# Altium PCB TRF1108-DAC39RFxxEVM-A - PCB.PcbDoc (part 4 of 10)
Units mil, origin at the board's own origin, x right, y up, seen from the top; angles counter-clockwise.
Board outline 4951.22 x 2726.56 mil, 16 copper layers (Top Layer, L2 GND1, L3 PWR1, L4 GND2, L5 PWR2, L6 GND3, L7 Ctrl Signal 1, L8 GND4, L9 GND5, L10 Ctrl Signal 2, L11 GND6, L12 PWR3, L13 GND7, L14 PWR4, L15 GND8, Bottom Layer), stack 80.2 mil thick; 705 components, 433 nets, 3633 pads, 1678 vias.
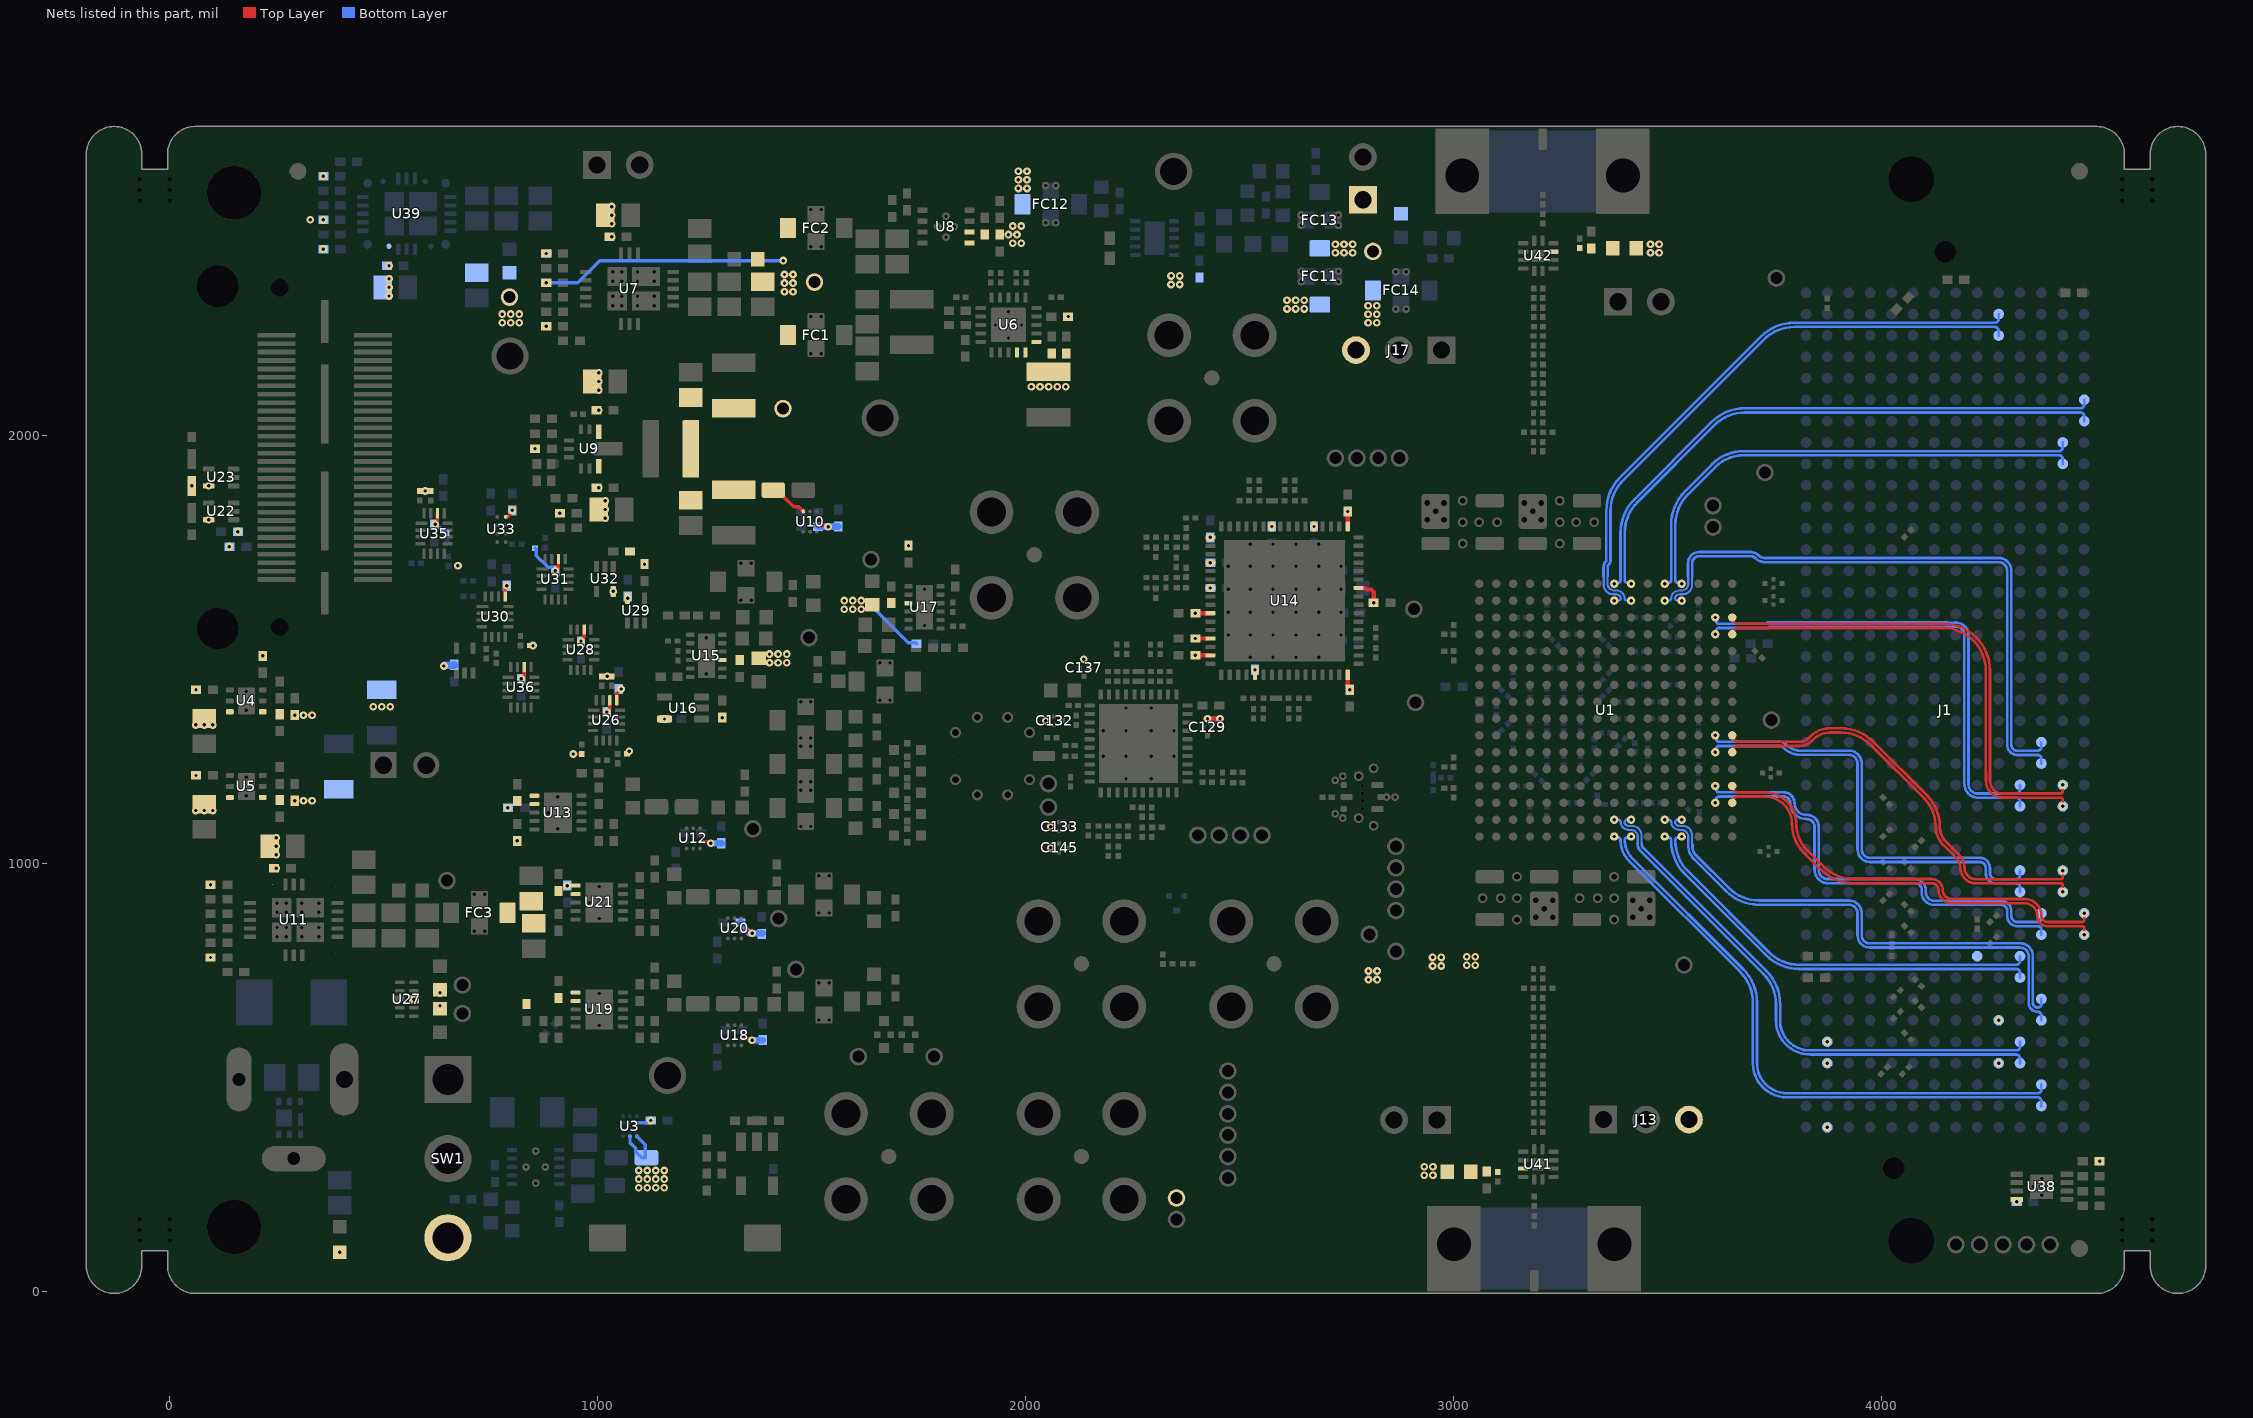
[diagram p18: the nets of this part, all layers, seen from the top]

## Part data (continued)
Logo3: library part cmp00102, "FCC_disclaimer", Alt Manufacturer=-
Logo4: library part cmp00317, Alt Manufacturer=-, PartNumber="ESD Logo"
Logo5: library part cmp00101, Alt Manufacturer=-, PartNumber=WEEE_Minimum
LOGO6: library part cmp00103, "CE_Mark", Alt Manufacturer=-
Logo7: library part cmp00104, "Texas Instrument Corporate Signature", Alt Manufacturer=-, PartNumber="TI Bug"
MP1: library part cmp00111, "Heat Sink Passive BGA Straight Adhesive 9.3C/W Black Anodized", Alt Manufacturer=-, Manufacturer="Advanced Thermal Solutions", Supplier Part Number 1=ATS1230-ND
MP5: library part cmp00110, "Fan Tubeaxial 5VDC Square - 17mm L x 17mm H Sleeve 0.636 CFM (0.018m³/min) 2 Wire Leads", Alt Manufacturer=-, Manufacturer="Nidec Copal", PartNumber=F17HA-05HC, Supplier Part Number 1=563-1426-ND
PP1 PP2 PP3 PP4 PP5 PP6 PP7 PP8 PP9 PP10 PP11 PP12 PP13 PP14 PP15 PP16 PP17 PP18 PP19 PP20 PP21 PP22 PP23 PP24 PP25 PP26 PP27 PP28 PP29 PP30 PP31 PP32 PP33 PP34 PP35 PP36 PP37 PP38 PP39 PP40 PP41 PP42 PP43 PP44 PP45 PP46 PP47 PP48 PP49 PP50 PP51: library part cmp00025, "Probe Point that can be used in lue of a test point", Alt Manufacturer=-
Q1: library part CMP-0000207-1, "MOSFET, N-CH, 20 V, 10 A, DQK0006C (WSON-6)", Alternate Manufacturer=None, Manufacturer="Texas Instruments", Supplier Part Number 1=CSD15571Q2-ND, Value1=19, Value2="2.5 nC"
R1 R36 R57: library part OtherRs00002, "RES SHUNT, 0603, 0.002 OHM, 1%,", Manufacturer="Stackpole Electronics Inc", Operating Temperature="-55°C ~ 155°C", Power (Watts)="0.333W, 1/3W", Ratings=AEC-Q200, Resistance="2 mΩ", Supplier Part Number 1=738-CSS0603FT2L00CT-ND, Temperature Coefficient=±150ppm/°C, Tolerance=±1%
R2: library part RSMD040200026, "RES SMD 1M OHM 1% 1/10W 0402", Manufacturer="Panasonic Electronic Components", Operating Temperature="-55°C ~ 155°C", Power (Watts)="0.1W, 1/10W", Ratings=AEC-Q200, Resistance="1 MΩ", Supplier Part Number 1=P1.00MLCT-ND, Temperature Coefficient=±100ppm/°C, Tolerance=±1%
R3: library part RSMD040202774, "RES SMD 45.3K OHM 1% 1/10W 0402", Manufacturer="Panasonic Electronic Components", Operating Temperature="-55°C ~ 155°C", Power (Watts)="0.1W, 1/10W", Ratings=AEC-Q200, Resistance="45.3 kΩ", Supplier Part Number 1=P45.3KLCT-ND, Temperature Coefficient=±100ppm/°C, Tolerance=±1%
R4 R8 R9 R11 R15 R17 R20 R25 R28 R31 R34 R35 R39 R48 R49 R51 R58 R84 R86 R88 R89 R91 R97 R106 R111 R112 R114 R115 R150 R151 R156 R161 R163 R178 R181 R183 R189 R210 R213 R214 R215: library part RSMD040202585, "RES SMD 4.7K OHM 5% 1/10W 0402", Manufacturer="Panasonic Electronic Components", Operating Temperature="-55°C ~ 155°C", Power (Watts)="0.1W, 1/10W", Ratings=AEC-Q200, Resistance="4.7 kΩ", Supplier Part Number 1=P4.7KJCT-ND, Temperature Coefficient=±200ppm/°C, Tolerance=±5%
R5: library part RSMD080500627, "RES SMD 2.2K OHM 1% 1/8W 0805", Manufacturer="Panasonic Electronic Components", Operating Temperature="-55°C ~ 155°C", Power (Watts)="0.125W, 1/8W", Ratings=AEC-Q200, Resistance="2.2 kΩ", Temperature Coefficient=±100ppm/°C, Tolerance=±1%
R6 R7: library part RSMD120607282, "RES 0 OHM JUMPER 1206 SMD", Manufacturer="Vishay Dale", Operating Temperature="-55°C ~ 155°C", Power (Watts)="0.25W, 1/4W", Ratings=AEC-Q200, Resistance="0 Ω", Temperature Coefficient=-, Tolerance=Jumper
R10: library part RSMD040201180, "RES SMD 2M OHM 5% 1/10W 0402", Manufacturer="Panasonic Electronic Components", Operating Temperature="-55°C ~ 155°C", Power (Watts)="0.1W, 1/10W", Ratings=AEC-Q200, Resistance="2 MΩ", Supplier Part Number 1=P2.0MJCT-ND, Temperature Coefficient="-400/ +150ppm/°C", Tolerance=±5%
R12: library part RSMD040202017, "RES SMD 3.6M OHM 5% 1/10W 0402", Manufacturer="Panasonic Electronic Components", Operating Temperature="-55°C ~ 155°C", Power (Watts)="0.1W, 1/10W", Ratings=AEC-Q200, Resistance="3.6 MΩ", Supplier Part Number 1=P3.6MJCT-ND, Temperature Coefficient="-400/ +150ppm/°C", Tolerance=±5%
R13 R14: library part RSMD040200111, "RES SMD 1.2M OHM 5% 1/10W 0402", Manufacturer="Panasonic Electronic Components", Operating Temperature="-55°C ~ 155°C", Power (Watts)="0.1W, 1/10W", Ratings=AEC-Q200, Resistance="1.2 MΩ", Supplier Part Number 1=P1.2MJCT-ND, Temperature Coefficient="-400/ +150ppm/°C", Tolerance=±5%
R16 R170: library part RSMD040200354, "RES SMD 100K OHM 5% 1/10W 0402", Manufacturer="Panasonic Electronic Components", Operating Temperature="-55°C ~ 155°C", Power (Watts)="0.1W, 1/10W", Ratings=AEC-Q200, Resistance="100 kΩ", Supplier Part Number 1=P100KJCT-ND, Temperature Coefficient=±200ppm/°C, Tolerance=±5%
R18 R37 R38 R43 R54 R55 R93 R94 R101 R102 R103 R107 R113 R116 R171 R172 R173 R174 R204: library part RSMD040200001, "RES SMD 0 OHM JUMPER 1/10W 0402", Manufacturer="Panasonic Electronic Components", Operating Temperature="-55°C ~ 155°C", Power (Watts)="0.1W, 1/10W", Ratings=AEC-Q200, Resistance="0 Ω", Supplier Part Number 1=P0.0JCT-ND, Temperature Coefficient=-, Tolerance=Jumper
R19 R21 R22 R23 R24 R26 R46 R63 R65 R68 R70 R119 R120 R121 R124 R133 R136 R142 R143 R144 R145 R146 R147 R152 R153 R154 R155 R157 R158 R159 R160 R162 R164 R165 R166 R167 R168 R169 R175 R186 R187 R200 R205 R206 R207 R209 R211 R212 R216 R217 R218 R219 R220 R221 R222 R223 R224 R225 R226 R227 R228 R229 R230 R231 R236 R250 R255: library part RSMD020101699, "RES SMD 0 OHM JUMPER 1/20W 0201", Manufacturer="Panasonic Electronic Components", Operating Temperature="-55°C ~ 125°C", Power (Watts)="0.05W, 1/20W", Resistance="0 Ω", Supplier Part Number 1=P15979CT-ND, Tolerance=Jumper
R27 R29 R182: library part RSMD040201047, "RES SMD 18.2K OHM 1% 1/10W 0402", Manufacturer="Panasonic Electronic Components", Operating Temperature="-55°C ~ 155°C", Power (Watts)="0.1W, 1/10W", Ratings=AEC-Q200, Resistance="18.2 kΩ", Supplier Part Number 1=P18.2KLCT-ND, Temperature Coefficient=±100ppm/°C, Tolerance=±1%
R30 R41 R53 R180: library part RSMD040202616, "RES SMD 4.87K OHM 1% 1/10W 0402", Manufacturer="Panasonic Electronic Components", Operating Temperature="-55°C ~ 155°C", Power (Watts)="0.1W, 1/10W", Ratings=AEC-Q200, Resistance="4.87 kΩ", Supplier Part Number 1=P4.87KLCT-ND, Temperature Coefficient=±100ppm/°C, Tolerance=±1%
R32: library part RSMD040202088, "RES SMD 30.9K OHM 1% 1/10W 0402", Manufacturer="Panasonic Electronic Components", Operating Temperature="-55°C ~ 155°C", Power (Watts)="0.1W, 1/10W", Ratings=AEC-Q200, Resistance="30.9 kΩ", Supplier Part Number 1=P30.9KLCT-ND, Temperature Coefficient=±100ppm/°C, Tolerance=±1%
R33 R40 R44 R45 R47 R56 R82 R83 R95 R104: library part RSMD040200316, "RES 10K OHM 1% 1/10W 0402", Manufacturer="Panasonic Electronic Components", Operating Temperature="-55°C ~ 175°C", Power (Watts)="0.1W, 1/10W", Ratings=AEC-Q200, Resistance="10 kΩ", Supplier Part Number 1=10-ERJ-H2RF1002XCT-ND, Temperature Coefficient=±100ppm/°C, Tolerance=±1%
R42: library part RSMD040200983, "RES SMD 17.4K OHM 1% 1/10W 0402", Manufacturer="Panasonic Electronic Components", Operating Temperature="-55°C ~ 155°C", Power (Watts)="0.1W, 1/10W", Ratings=AEC-Q200, Resistance="17.4 kΩ", Supplier Part Number 1=P17.4KLCT-ND, Temperature Coefficient=±100ppm/°C, Tolerance=±1%
R50: library part RSMD040203921, "RES SMD 9.31K OHM 1% 1/10W 0402", Manufacturer="Panasonic Electronic Components", Operating Temperature="-55°C ~ 155°C", Power (Watts)="0.1W, 1/10W", Ratings=AEC-Q200, Resistance="9.31 kΩ", Supplier Part Number 1=P9.31KLCT-ND, Temperature Coefficient=±100ppm/°C, Tolerance=±1%
R52: library part RSMD040203072, "RES SMD 52.3K OHM 1% 1/10W 0402", Manufacturer="Panasonic Electronic Components", Operating Temperature="-55°C ~ 155°C", Power (Watts)="0.1W, 1/10W", Ratings=AEC-Q200, Resistance="52.3 kΩ", Supplier Part Number 1=P52.3KLCT-ND, Temperature Coefficient=±100ppm/°C, Tolerance=±1%
R59: library part RSMD040203879, "RES SMD 88.7K OHM 1% 1/10W 0402", Manufacturer="Panasonic Electronic Components", Operating Temperature="-55°C ~ 155°C", Power (Watts)="0.1W, 1/10W", Ratings=AEC-Q200, Resistance="88.7 kΩ", Supplier Part Number 1=P88.7KLCT-ND, Temperature Coefficient=±100ppm/°C, Tolerance=±1%
R60: library part RSMD040200547, "RES SMD 12.4K OHM 1% 1/10W 0402", Manufacturer="Panasonic Electronic Components", Operating Temperature="-55°C ~ 155°C", Power (Watts)="0.1W, 1/10W", Ratings=AEC-Q200, Resistance="12.4 kΩ", Supplier Part Number 1=P12.4KLCT-ND, Temperature Coefficient=±100ppm/°C, Tolerance=±1%
R61: library part RSMD040200530, "RES 12K OHM 0.5% 1/10W 0402 SMD", Manufacturer="Panasonic Electronic Components", Operating Temperature="-55°C ~ 155°C", Power (Watts)="0.1W, 1/10W", Ratings=AEC-Q200, Resistance="12 kΩ", Supplier Part Number 1=10-ERJ-U2RD1202XCT-ND, Temperature Coefficient=±50ppm/°C, Tolerance=±0.5%
R62 R66 R67 R71 R125 R126 R129 R130 R131 R132 R138 R139 R140 R141: library part RSMD020100177, "RES SMD 49.9 OHM 1% 1/20W 0201", Manufacturer="Panasonic Electronic Components", Operating Temperature="-55°C ~ 125°C", Power (Watts)="0.05W, 1/20W", Resistance="49.9 Ω", Supplier Part Number 1=P123049CT-ND, Temperature Coefficient=±200ppm/°C, Tolerance=±1%
R64 R69 R122 R123 R128: library part RSMD020100289, "RES SMD 100 OHM 1% 1/20W 0201", Manufacturer="Panasonic Electronic Components", Operating Temperature="-55°C ~ 125°C", Power (Watts)="0.05W, 1/20W", Resistance="100 Ω", Supplier Part Number 1=P122654CT-ND, Temperature Coefficient=±200ppm/°C, Tolerance=±1%
R72 R73 R74 R75 R76 R77 R78 R79 R80 R81: library part RSMD020100156, "RES SMD 120 OHM 1% 1/20W 0201", Manufacturer="Panasonic Electronic Components", Operating Temperature="-55°C ~ 125°C", Power (Watts)="0.05W, 1/20W", Resistance="120 Ω", Supplier Part Number 1=P122692CT-ND, Temperature Coefficient=±200ppm/°C, Tolerance=±1%
R85 R90: library part RSMD040201710, "RES SMD 255K OHM 1% 1/10W 0402", Manufacturer="Panasonic Electronic Components", Operating Temperature="-55°C ~ 155°C", Power (Watts)="0.1W, 1/10W", Ratings=AEC-Q200, Resistance="255 kΩ", Supplier Part Number 1=P255KLCT-ND, Temperature Coefficient=±100ppm/°C, Tolerance=±1%
R87 R92: library part RSMD040202914, "RES SMD 499K OHM 1% 1/10W 0402", Manufacturer="Panasonic Electronic Components", Operating Temperature="-55°C ~ 155°C", Power (Watts)="0.1W, 1/10W", Ratings=AEC-Q200, Resistance="499 kΩ", Supplier Part Number 1=P499KLCT-ND, Temperature Coefficient=±100ppm/°C, Tolerance=±1%
R96 R105: library part OtherRs00005, "RES SHUNT, 0603, 0.02 OHM, 1%, 0", Manufacturer="Stackpole Electronics Inc", Operating Temperature="-55°C ~ 155°C", Power (Watts)="0.333W, 1/3W", Ratings=AEC-Q200, Resistance="20 mΩ", Supplier Part Number 1=738-CSS0603FT20L0CT-ND, Temperature Coefficient=±75ppm/°C, Tolerance=±1%
R98 R108: library part RSMD040200493, "RES SMD 115K OHM 1% 1/10W 0402", Manufacturer="Panasonic Electronic Components", Operating Temperature="-55°C ~ 155°C", Power (Watts)="0.1W, 1/10W", Ratings=AEC-Q200, Resistance="115 kΩ", Supplier Part Number 1=P115KLCT-ND, Temperature Coefficient=±100ppm/°C, Tolerance=±1%
R99 R109: library part RSMD040202211, "RES SMD 33K OHM 1% 1/10W 0402", Manufacturer="Panasonic Electronic Components", Operating Temperature="-55°C ~ 155°C", Power (Watts)="0.1W, 1/10W", Ratings=AEC-Q200, Resistance="33 kΩ", Supplier Part Number 1=P33.0KLCT-ND, Temperature Coefficient=±100ppm/°C, Tolerance=±1%
R100 R110: library part RSMD040203274, "RES SMD 6.65K OHM 1% 1/10W 0402", Manufacturer="Panasonic Electronic Components", Operating Temperature="-55°C ~ 155°C", Power (Watts)="0.1W, 1/10W", Ratings=AEC-Q200, Resistance="6.65 kΩ", Supplier Part Number 1=P6.65KLCT-ND, Temperature Coefficient=±100ppm/°C, Tolerance=±1%
R117 R118: library part RSMD020100281, "RES SMD 66.5 OHM 1% 1/20W 0201", Manufacturer="Panasonic Electronic Components", Operating Temperature="-55°C ~ 125°C", Power (Watts)="0.05W, 1/20W", Resistance="66.5 Ω", Supplier Part Number 1=P123123CT-ND, Temperature Coefficient=±200ppm/°C, Tolerance=±1%
R127 R135: library part RSMD020100110, "RES SMD 82.5 OHM 1% 1/20W 0201", Manufacturer="Panasonic Electronic Components", Operating Temperature="-55°C ~ 125°C", Power (Watts)="0.05W, 1/20W", Resistance="82.5 Ω", Supplier Part Number 1=P123178CT-ND, Temperature Coefficient=±200ppm/°C, Tolerance=±1%
R134 R137: library part RSMD020100121, "RES SMD 130 OHM 1% 1/20W 0201", Manufacturer="Panasonic Electronic Components", Operating Temperature="-55°C ~ 125°C", Power (Watts)="0.05W, 1/20W", Resistance="130 Ω", Supplier Part Number 1=P122712CT-ND, Temperature Coefficient=±200ppm/°C, Tolerance=±1%
R148 R149: library part RSMD060301484, "RES SMD 2.2K OHM 5% 1/10W 0603", Manufacturer="Panasonic Electronic Components", Operating Temperature="-55°C ~ 155°C", Power (Watts)="0.1W, 1/10W", Ratings=AEC-Q200, Resistance="2.2 kΩ", Supplier Part Number 1=P2.2KGCT-ND, Temperature Coefficient=±200ppm/°C, Tolerance=±5%
R176: library part RSMD040200006, "RES SMD 1K OHM 1% 1/10W 0402", Manufacturer="Panasonic Electronic Components", Operating Temperature="-55°C ~ 155°C", Power (Watts)="0.1W, 1/10W", Ratings=AEC-Q200, Resistance="1 kΩ", Supplier Part Number 1=P1.00KLCT-ND, Temperature Coefficient=±100ppm/°C, Tolerance=±1%
R177: library part RSMD040202006, "RES SMD 3.6K OHM 1% 1/10W 0402", Manufacturer="Panasonic Electronic Components", Operating Temperature="-55°C ~ 155°C", Power (Watts)="0.1W, 1/10W", Ratings=AEC-Q200, Resistance="3.6 kΩ", Supplier Part Number 1=P3.60KLCT-ND, Temperature Coefficient=±100ppm/°C, Tolerance=±1%
R179: library part CMP-0026220-2, "RES, 28.7 k, 1%, 0.063 W, AEC-Q200 Grade 0, 0402", Manufacturer=Vishay-Dale, Power_W=63mW, Supplier Part Number 1=541-28.7KLCT-ND, TempCo="100 ppm/C", Tolerance_%=1%, Value2=0.063W, Value_Code=28k7, ValueDisplayed=28.7k
R184: library part CMP-0022744-5, "RES, 10.5 k, 1%, 0.1 W, 0603", Manufacturer=Yageo, Power_W=100mW, Supplier Part Number 1=311-10.5KHRCT-ND, TempCo="100 ppm/C", Tolerance_%=1%, Value2=0.1W, Value_Code=10k5, ValueDisplayed=10.5k
R185: library part CMP-0023000-5, "RES, 2.00 k, 1%, 0.1 W, 0603", Manufacturer=Yageo, Power_W=100mW, Supplier Part Number 1=311-2.00KHRCT-ND, TempCo="100 ppm/C", Tolerance_%=1%, Value2=0.1W, Value_Code=2k00, ValueDisplayed=2.00k
R192 R237 R242 R256: library part RSMD020100157, "RES SMD 140 OHM 1% 1/20W 0201", Manufacturer="Panasonic Electronic Components", Operating Temperature="-55°C ~ 125°C", Power (Watts)="0.05W, 1/20W", Resistance="140 Ω", Supplier Part Number 1=P122727CT-ND, Temperature Coefficient=±200ppm/°C, Tolerance=±1%
R196 R197 R201 R202 R246 R247 R251 R252: library part RSMD020101700, "Thick Film Resistors - SMD 8.66Ohms 1/20W 0201 1%", Manufacturer=Yageo, Operating Temperature="-55°C ~ 125°C", Power (Watts)="0.05W, 1/20W", Resistance="8.66 Ω", Supplier Part Number 1=13-RC0201FR-078R66LCT-ND, Temperature Coefficient="- 100 PPM / C, + 350 PPM / C", Tolerance=±1%
R208 R232 R233 R234: library part RSMD040200370, "RES SMD 100 OHM 5% 1/10W 0402", Manufacturer="Panasonic Electronic Components", Operating Temperature="-55°C ~ 155°C", Power (Watts)="0.1W, 1/10W", Ratings=AEC-Q200, Resistance="100 Ω", Supplier Part Number 1=P100JCT-ND, Temperature Coefficient=±200ppm/°C, Tolerance=±5%
SH-J13 SH-J14 SH-J17 SH-J18: library part CMP-0003761-1, "Shunt, 2.54mm, Gold, Black", Manufacturer="Wurth Elektronik", Supplier Part Number 1=732-2678-ND
SW1: library part cmp00021, "Switch Slide SPDT 120V, 6A", Alt Manufacturer=-, Manufacturer="C&K Components", Supplier Part Number 1=CKN9628-ND
SW2: library part cmp00234, "SWITCH TACTILE SPST-NO 0.05A 24V", Alt Manufacturer=-, Manufacturer="TE Connectivity", Supplier Part Number 1=A101402CT-ND
T1: library part cmp00236, "1:2 LTCC Transformer, 4700 - 12000 MHz, 50Ω", Alt Manufacturer=-, Manufacturer=Mini-Circuits, Supplier Part Number 1=3157-NCR2-123+CT-ND
T2 T3 T4 T5: library part cmp00081, "Signal Conditioning BIAS TEE SURFACE MOUNT", Alt Manufacturer=-, Manufacturer=Mini-Circuits, Supplier Part Number 1=3157-TCBT-123+CT-ND
TP1 TP2 TP3: library part cmp00041, "Test Point, Multipurpose, Black, TH", Alt Manufacturer=-, Color=Black, Manufacturer=Keystone, Supplier Part Number 1=36-5011-ND
TP4: library part cmp00040, "Test Point, Multipurpose, Red, TH", Alt Manufacturer=-, Color=Red, Manufacturer=Keystone, Supplier Part Number 1=36-5010-ND
U1: library part cmp00276, Alt Manufacturer=-, Manufacturer="Texas Instruments"
U2: library part cmp00157, "12V, 5A, 30mΩ eFuse with Adjustable +/-15% Accurate Current Limit, DRC0010J (VSON-10)", Alt Manufacturer=-, Manufacturer="Texas Instruments"
U3 U10 U12 U18 U20: library part cmp00264, "28-V, 16-Bit, I2C Output Current, Voltage and Power Monitor With Alert in WCSP Package", Alt Manufacturer="Texas Instruments", Alt PartNumber=INA231AIYFFT, Color=-, Supplier Part Number 1=296-41263-1-ND
U4 U5: library part cmp00251, "300-mA, 18-V, Ultra-Low IQ, Low-Dropout Linear Voltage Regulator With Power-Good", Alt Manufacturer=-, Manufacturer="Texas Instruments", PartNumber=TPS7A2501DRV
U6: library part cmp00163, "Regulators 2-A, low-VIN (1.1-V), low-noise, high-accuracy, ultra-low-dropout voltage regulator with power good", Alt Manufacturer=-, Manufacturer="Texas Instruments"
U7 U11: library part cmp00201, "3-V to 17-V, 2-A/3-A Low-Noise and Low-Ripple Buck Power Module with Integrated Ferrite Bead Filter Compensation", Alt Manufacturer=-, Manufacturer="Texas Instruments", Max Supply Voltage=17V, Min Supply Voltage=3V, Nominal Supply Current=5mA, Operating Temperature Range="-55°C to +125°C", Output Voltage=0.8-5.5V, PartNumber=TPSM82913RDU, Switching Frequency=1/2.2MHz
U8: library part cmp00168, "1-A, high-PSRR, ultra-low-dropout voltage regulator with low-IQ & enable", Alt Manufacturer=-, Manufacturer="Texas Instruments"
U9: library part cmp00293, "4-V to 18-V Input, 6-A Synchronous SWIFT™ Step-Down Converter with Internally Compensated Advanced Current Mode Control", Alt Manufacturer=-, Manufacturer="Texas Instruments", Supplier Part Number 1=296-TPS543620RPYRCT-ND
U13 U19 U21: library part cmp00169, "1-A, ultra-low noise, ultra-high PSRR, RF voltage regulator", Alt Manufacturer=-, Manufacturer="Texas Instruments", Supplier Part Number 1=296-TPS7A9401DSCRCT-ND
U14: library part cmp00252, "Ultra low-noise JESD204B compliant clock jitter cleaner with integrated 2370 to 2630-MHz VCO0", Alt Manufacturer="Texas Instruments", Alt PartNumber=LMK04828BISQE/NOPB, Color=-, Supplier Part Number 1=296-40278-1-ND
U15 U17: library part cmp00189, "Low-Noise Positive- and Negative-Output Charge Pump With Integrated LDO", Alt Manufacturer=-, Manufacturer="Texas Instruments"
U16: library part cmp00128, "Single Bus Inverting Buffer Gate", Alt Manufacturer=-, Manufacturer="Texas Instruments"
U22 U23 U29 U32 U34: library part cmp00309, "Single Bus Buffer Gate With 3-State Outputs", Alt Manufacturer=-, Manufacturer="Texas Instruments"
U24: library part cmp00312, "Signal Conditioning 50 ohm 2 terminal Power Splitter", Alt Manufacturer=-, Manufacturer=Susumu, Supplier Part Number 1=754-PS1608GT2-R50-T1
U25: library part cmp00153, "High Frequency SYSREF Buffer/Multiplier/Divider", Alt Manufacturer="Texas Instruments", Alt PartNumber=LMX1204RHAR, Color=-
U26 U30 U35: library part cmp00171, "Translation - Voltage Levels 4-bit dual-supply bus transceiver with 3-state outputs and independent direction control inputs", Alt Manufacturer="Texas Instruments", Alt PartNumber=SN74AXC4T774RSV, Color=-, Supplier Part Number 1=296-24741-1-ND
U27: library part cmp00307, "5-V low-leakage-current, 2: 1, 2-channel precision analog switch", Alt Manufacturer=-, Manufacturer="Texas Instruments", Supplier Part Number 1=296-TMUX1136DQARCT-ND
U28 U31 U36: library part cmp00269, "Low-Voltage 4-Bit 1-of-2 FET Multiplexer/Demultiplexe", Alt Manufacturer=-, Manufacturer="Texas Instruments", Supplier Part Number 1=296-35586-1-ND
U33: library part cmp00311, "Dual-Bit Dual-Supply Bus Transceiver With Configurable Voltage Translation And 3-State Outputs", Alt Manufacturer=-, Manufacturer="Texas Instruments", PartNumber=SN74AVC2T45YZPR
U37: library part cmp00229, "Push-pull, supply voltage supervisor with manual reset", Alt Manufacturer=-, Manufacturer="Texas Instruments"
U38: library part cmp00154, "EEPROM 64K 8KX8 1.8V SER EE IND 1/4AWP RPO", Alt Manufacturer=-, Manufacturer=Microchip, Manufacturer_Part_Number=24AA64FT-I/MNY, Supplier Part Number 1=24LC64FT-I/MNYCT-ND
U39: library part CMP-0094706-3, "3-V to 17-V, 2-A Low Noise and Low Ripple Buck Converter Module with Integrated Ferrite Bead Filter Compensation", Manufacturer="Texas Instruments", Max Supply Voltage=17V, Min Supply Voltage=3V, Nominal Supply Current=5mA, Operating Temperature Range="-55°C to +125°C", Output Voltage=0.8-5.5V, Switching Frequency=1/2.2MHz
U40: library part CMP-0861069-1, "2A High-Accuracy Low-Noise Low-Dropout (LDO) Voltage Regulator, DSK0010A (WSON-10)", Alternate Manufacturer="Texas Instruments", Alternate PartNumber=TPS7A9201DSKT, Operating Temperature Range="-40 to 125 C", Rating=Catalog
U41 U42: library part CMP-0090474-3, "RF IC", Manufacturer="Texas Instruments", Operating Temperature Range=to, Part Number=TRF1208RPVR
ZZ1: library part CMP-0003616-3
ZZ2: library part CMP-0077236-1
ZZ3: library part CMP-0077237-1
ZZ4: library part CMP-0077238-1

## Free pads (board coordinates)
  round 0 hole 10 unplated mask+0: 3(-70,2548.03) 3(-70,2573.03) 3(-70,2598.03) 3(-70,118.5) 3(-70,143.5) 3(-70,168.5) 3(0,2548.03) 3(0,2573.03) 3(0,2598.03) 3(0,118.5) 3(0,143.5) 3(0,168.5) 3(4561.81,118.5) 3(4561.81,143.5) 3(4561.81,168.5) 3(4561.81,2548.03) 3(4561.81,2573.03) 3(4561.81,2598.03) 3(4631.81,118.5) 3(4631.81,143.5) 3(4631.81,168.5) 3(4631.81,2548.03) 3(4631.81,2573.03) 3(4631.81,2598.03)

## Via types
v1: diameter 18, hole 8, Top Layer to Bottom Layer, tented both sides, 1468 vias
v2: diameter 20, hole 10.01, Top Layer to Bottom Layer, 187 vias
v3: diameter 19.68, hole 7.87, Top Layer to Bottom Layer, tented both sides, 16 vias
v4: diameter 19.68, hole 7.87, Top Layer to Bottom Layer, 6 vias
v5: diameter 18/18/18/18/18/18/18/18/18/18/18/18/18/18/18/18 (per signal layer), hole 8, Top Layer to Bottom Layer, tented both sides, 1 vias

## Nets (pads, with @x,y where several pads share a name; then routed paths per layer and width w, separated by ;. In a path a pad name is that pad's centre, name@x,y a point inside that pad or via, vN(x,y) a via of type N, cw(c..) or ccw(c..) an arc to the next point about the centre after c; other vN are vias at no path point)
0SRX_n: J1.A38 U1.A7 | length 1381.4
  Bottom Layer w6.25: v1(3414.14,1062.51) cw(c3408.71,1067.94) 3408.71,1060.26 3405.73,1060.26 ccw(c3405.73,1053.86) 3401.2,1058.39 ccw(c3405.73,1053.86) 3399.33,1053.86 ccw(c3458.38,1053.86) 3416.62,1012.11 3676.25,752.48 cw(c3598.65,674.87) 3708.4,674.87 3708.4,533.06 ccw(c3778.52,533.06) 3778.52,462.93 4363.97,462.93 ccw(c4363.97,471.77) 4372.81,471.77 J1.A38@4372.81,483.06
0SRX_p: J1.A39 U1.A8 | length 1396.7
  Bottom Layer w6.25: v1(3374.77,1062.51) ccw(c3380.19,1067.94) 3380.19,1060.26 3383.18,1060.26 cw(c3383.18,1053.86) 3387.7,1058.39 cw(c3383.18,1053.86) 3389.58,1053.86 ccw(c3458.38,1053.86) 3409.73,1005.21 3669.36,745.58 cw(c3598.65,674.87) 3698.65,674.87 3698.65,533.06 ccw(c3778.52,533.06) 3778.52,453.18 4363.97,453.18 cw(c4363.97,444.34) 4372.81,444.34 J1.A39@4372.81,433.06
1p0V_DAC: C33.2 C34.2 C35.2 C36.2 L1.2 PP2.1 R36.2 U10.D3 | length 91.2
  Top Layer w8: R36.2@1409.88,1871.8 1422.77,1858.91 1431.71,1858.91 1457.94,1832.68 1469.48,1832.68 U10.D3@1480.35,1821.8
1SRX_n: J1.B36 U1.B7 | length 1253.5
  Bottom Layer w5: v1(3414.14,1101.88) 3404.81,1101.88 ccw(c3404.81,1096.02) 3398.95,1096.02 ccw(c3406.5,1096.02) 3401.16,1090.69 ccw(c3409.97,1099.49) 3409.97,1087.04 3416.9,1087.04 cw(c3416.9,1065.26) 3438.69,1065.26 3438.69,1045.56
  Bottom Layer w6.25: 3438.87,1045.37 ccw(c3452.65,1045.37) 3442.91,1035.63 3730.15,748.39 cw(c3652.55,670.78) 3762.3,670.78 3762.3,630.34 ccw(c3829.7,630.34) 3763.25,619.03 ccw(c3769.41,620.08) 3763.29,618.85 ccw(c3832.67,633.3) 3818.22,563.92 ccw(c3819.45,570.05) 3818.37,563.89 ccw(c3829.7,630.34) 3829.7,562.93 4313.97,562.93 ccw(c4313.97,571.77) 4322.81,571.77 J1.B36@4322.81,583.06
1SRX_p: J1.B37 U1.B8 | length 1266.9
  Bottom Layer w5: v1(3374.77,1101.88) 3384.09,1101.88 cw(c3384.09,1096.02) 3389.95,1096.02 3389.95,1095.97 ccw(c3406.36,1095.97) 3394.76,1084.36 ; 3394.86,1084.26 ccw(c3409.88,1099.28) 3409.88,1078.04 3414.06,1078.04 cw(c3414.06,1062.41) 3429.69,1062.41 3429.69,1045.52
  Bottom Layer w6.25: 3429.12,1045.41 ccw(c3452.75,1045.41) 3436.04,1028.71 3723.26,741.49 cw(c3652.55,670.78) 3752.55,670.78 3752.55,633.3 ccw(c3832.67,633.3) 3832.67,553.18 4313.97,553.18 cw(c4313.97,544.34) 4322.81,544.34 J1.B37@4322.81,533.06
2p3V_Analog_LDO: C45.2 C46.2 C49.2 C114.2 C123.2 FC3.3 R58.2 R97.2 R106.2 U13.1 U13.2 U19.1 U19.2 U21.1 U21.2
  other v1: 928.37,947.83 790,1130
2p5V_Clock: C12.2 C14.2 C129.1 C132.1 C133.1 C137.1 C145.1 C160.2 R18.2 U6.1 U6.19 U6.20 U26.13 | length 89.1
  Top Layer w8: U26.13@1044.07,1381.04 1044.07,1396.75 v1(1054.48,1407.16)
  Top Layer w12: v1(2424.57,1337.39) v1(2453.88,1337.39)
  Bottom Layer w12: v1(2424.57,1337.39) v1(2453.88,1337.39)
  other v1: 2058.04,1035.82 2058.04,1085.82 2046.51,1333.18 2135.79,1476.39 2013.29,2113 2033.29,2113 2053.29,2113 2073.29,2113 2093.29,2113
2SRX_n: J1.B32 U1.A4 | length 977.8
  Bottom Layer w6.25: v1(3532.25,1062.51) cw(c3526.82,1067.94) 3526.82,1060.26 3523.84,1060.26 ccw(c3523.84,1053.86) 3519.31,1058.39 ccw(c3523.84,1053.86) 3517.44,1053.86 3517.44,1052.39 ccw(c3617.44,1052.39) 3546.73,981.68 3736.19,792.22 ccw(c3806.9,862.93) 3806.9,762.93 4313.97,762.93 ccw(c4313.97,771.77) 4322.81,771.77 J1.B32@4322.81,783.06
2SRX_p: J1.B33 U1.A5 | length 993.1
  Bottom Layer w6.25: v1(3492.88,1062.51) ccw(c3498.31,1067.94) 3498.31,1060.26 3501.29,1060.26 cw(c3501.29,1053.86) 3505.81,1058.39 cw(c3501.29,1053.86) 3507.69,1053.86 3507.69,1052.39 ccw(c3617.44,1052.39) 3539.83,974.78 3729.29,785.33 ccw(c3806.9,862.93) 3806.9,753.18 4313.97,753.18 cw(c4313.97,744.34) 4322.81,744.34 J1.B33@4322.81,733.06
3p3V_Clock: C26.2 C67.2 C68.2 C69.2 C70.2 C71.2 C72.2 C77.2 C78.2 C79.2 C80.2 C81.2 C82.2 R32.2 U8.1 U8.2 U14.10 U14.17 U14.21 U14.26 U14.33 U14.36 U14.39 U14.42 U14.45 U14.47 U14.53 U14.64 | length 241.7
  Top Layer w10: v1(2396.3,1485.74) U14.47@2431.3,1485.74 ; v1(2396.3,1525.11) U14.45@2431.3,1525.11 ; v1(2396.3,1584.17) U14.42@2431.3,1584.17 ; U14.64@2752.17,1440.46 2752.17,1412.35 2757.09,1407.43 v1(2757.09,1405.46) ; U14.17@2752.17,1786.92 v1(2752.17,1821.92) ; U14.10@2777.76,1643.22 2791.99,1643.22 2795.3,1639.91 2806.9,1639.91 2812.76,1634.05 v1(2812.76,1608.22)
  other v1: 2535.63,1452.28 2431.3,1643.22 2431.3,1702.28 2431.3,1761.33 2575,1786.92 2673.43,1786.92 1969.53,2448.9 1989.53,2448.9 1959.53,2468.9 1979.53,2468.9 1969.53,2488.9 1989.53,2488.9
3p3V_Utility: C4.1 C8.2 C37.1 C48.1 C96.1 C113.1 C122.1 C159.1 C161.1 C162.1 C164.2 C165.1 C167.1 C168.1 C169.1 C262.2 J13.3 J17.3 R8.2 R10.2 R15.2 R20.2 R34.2 R37.1 R48.2 R56.2 R84.2 R88.2 R102.1 R111.1 R112.1 R114.1 R115.1 R142.1 R143.1 R144.1 R146.2 R148.2 R149.2 R150.2 R151.1 R156.1 R157.2 R159.2 R161.2 R163.1 R164.1 R165.2 R166.1 R168.2 R183.2 R189.2 R210.2 U3.B1 U4.1 U10.B1 U12.B1 U16.5 U18.B1 U20.B1 U22.5 U23.5 U26.14 U27.8@570.56,682.33 U28.14 U29.5 U30.13 U31.14 U32.5 U33.A2 U35.14 U36.14 U38.8 | length 682.6
  Top Layer w8: R165.2@584.08,1869.72 v1(596.88,1869.72) ; v1(620.06,1791.73) 620.06,1794.44 625.57,1799.95 U35.14@625.57,1817.67 ; U30.13@784.07,1623.54 784.07,1642.33 787.57,1645.83 v1(787.57,1648.54) ; U33.A2@785.02,1809.41 785.23,1809.61 790.01,1809.61 795.57,1815.17 795.57,1817.25 800.02,1821.7 v1(800.02,1824.41) ; v1(821,1430.98) 821,1433.34 828.32,1440.66 U36.14@828.32,1458.54 ; v1(901,1683.48) 901,1685.84 908.32,1693.16 U31.14@908.32,1711.04 ; v1(942.74,1255.29) R144.1@962.74,1255.29 ; v1(961,1518.48) 961,1520.84 968.32,1528.16 U28.14@968.32,1546.04 ; v1(1021,1353.48) 1021,1355.84 1028.32,1363.16 U26.14@1028.32,1381.04 ; v1(1022.12,1436.83) R142.1@1032.8,1436.83 ; U12.B1@1239.08,1050.35 1257.74,1050.35 1261.37,1046.73 v1(1264.08,1046.73) ; U18.B1@1335.57,590.35 1354.24,590.35 1357.87,586.73 v1(1360.57,586.73) ; U20.B1@1335.57,840.35 1354.24,840.35 1357.87,836.73 v1(1360.57,836.73) ; U10.B1@1511.85,1790.31 1530.52,1790.31 1534.14,1786.68 v1@1536.85,1786.68
  Bottom Layer w8: C168.1@623.9,1783.92 631.08,1783.92 639.87,1775.13 644.7,1775.13 645,1774.83 R166.1@645,1770 ; R159.2@853.52,1736.04 854.31,1736.04 856.61,1733.74 856.61,1718.82 884.14,1691.29 895.15,1691.29 901,1685.45 v1(901,1683.48) ; U3.B1@1091.09,393.72 1119.33,393.72 C4.1@1123.76,398.15
  Bottom Layer w16: v1(1264.08,1046.73) C48.1@1289.08,1046.73 ; R102.1@1333.45,861.73 1335.42,861.73 1337.26,859.89 1337.26,853.34 1353.49,837.11 1360.19,837.11 v1(1360.57,836.73) C122.1@1385.57,836.73 ; v1(1360.57,586.73) C113.1@1385.57,586.73 ; R37.1@1514.72,1786.68 C37.1@1561.85,1786.68
  Bottom Layer w18: v1(640.74,1460.99) 642.13,1462.38 663.74,1462.38 664.58,1463.23 R163.1@664.58,1463.77
  other v1: 4315.24,209.51 4508.86,303.88 1123.76,399.15 631.56,667.45 570.56,682.33 631.56,697.2 95.4,949.98 811.87,1052.32 1073.47,1262.02 1155.97,1337.1 1291.37,1340.51 292.6,1346.14 312.6,1346.14 332.6,1346.14 217.6,1484.57 848.8,1508.72 1069.84,1619.48 1036.31,1635.17 673.37,1694.97 1109.21,1698.85 139.42,1740 1725.98,1742.11 159.37,1775 1538.21,1786.27 91.14,1802.56 51.14,1881.55 91.14,1881.93 853.54,1968.19 2099,2277.36 2339.5,2352.16 2359.5,2352.16 2359.5,2372.16 879.64,2424.63 359,2434.99
  other v5: 2339.5,2372.16
3P3VAUX-FMC: J1.D32
3p8V_Clock_LDO: C20.2 C97.2 C98.2 C105.2 C106.2 FB1.2 FC1.1 FC2.1 PP1.1 R27.2 R89.2 U15.3 U17.3 | length 746.3
  Bottom Layer w8: v1(879.64,2356.63) 953.51,2356.63 1005.04,2408.15 v1(1433.71,2408.15) ; v1(1615.98,1613.8) 1617.13,1612.65 1628.53,1612.65 1725.88,1515.31 1742.42,1515.31 R89.2@1745,1512.73
  other v1: 1401.37,1468.82 1421.37,1468.82 1441.37,1468.82 1401.37,1488.82 1421.37,1488.82 1441.37,1488.82 1575.98,1593.8 1595.98,1593.8 1615.98,1593.8 1575.98,1613.8 1595.98,1613.8 1436.29,2335.59 1456.29,2335.59 1436.29,2355.59 1456.29,2355.59 1436.29,2375.59 1456.29,2375.59
3SRX_n: J1.A34 U1.B4 | length 1198.8
  Bottom Layer w5: v1(3532.25,1101.88) 3522.92,1101.88 ccw(c3522.92,1096.02) 3517.06,1096.02 ccw(c3524.61,1096.02) 3519.27,1090.69 ccw(c3528.08,1099.49) 3528.08,1087.04 3535.01,1087.04 cw(c3535.01,1065.26) 3556.8,1065.26 3556.8,1045.56
  Bottom Layer w6.25: 3556.8,1045.56 cw(c3554.99,1043.75) 3557.36,1044.71 cw(c3554.99,1043.75) 3557.55,1043.75 3557.55,1036.05 ; 3557.55,1036.01 ccw(c3563.8,1036.21) 3557.64,1035.13 ccw(c3591.91,1041.52) 3558.09,1033.06 ccw(c3591.91,1041.52) 3563.09,1021.91 ccw(c3568.27,1025.4) 3563.74,1021.1 3642.48,942.35 ccw(c3713.19,1013.07) 3713.19,913.07 3923.1,913.07 cw(c3923.1,883.28) 3952.89,883.28 3952.89,832.08 ccw(c3972.01,832.08) 3972.01,812.95 4323.5,812.95 cw(c4323.5,783.76) 4352.69,783.76 4352.69,674.21 ccw(c4363.97,674.21) 4363.97,662.93 ccw(c4363.97,671.77) 4372.81,671.77 J1.A34@4372.81,683.06
3SRX_p: J1.A35 U1.B5 | length 1212.2
  Bottom Layer w5: v1(3492.88,1101.88) 3502.2,1101.88 cw(c3502.2,1096.02) 3508.06,1096.02 3508.06,1095.97 ccw(c3524.47,1095.97) 3512.87,1084.36 ; 3512.97,1084.26 ccw(c3527.99,1099.28) 3527.99,1078.04 3532.17,1078.04 cw(c3532.17,1062.41) 3547.8,1062.41 3547.8,1045.52
  Bottom Layer w6.25: 3547.55,1045.52 ccw(c3556.8,1045.56) 3547.7,1043.88 cw(c3541.55,1042.78) 3547.8,1042.82 3547.8,1041.52 ccw(c3591.91,1041.52) 3548.62,1033.06 ccw(c3591.91,1041.52) 3560.72,1010.33 3635.59,935.46 ccw(c3713.19,1013.07) 3713.19,903.32 3923.1,903.32 cw(c3923.1,883.28) 3943.14,883.28 3943.14,832.08 ccw(c3972.01,832.08) 3972.01,803.2 4323.5,803.2 cw(c4323.5,783.76) 4342.94,783.76 4342.94,674.21 ccw(c4363.97,674.21) 4363.97,653.18 cw(c4363.97,644.34) 4372.81,644.34 J1.A35@4372.81,633.06
4SRX_n: J1.Y30 U1.D1 | length 1014.4
  Top Layer w6.25: U1.D1@3650.36,1180.62 ccw(c3665.17,1180.62) 3665.17,1165.81 3726.23,1165.81 cw(c3726.23,1092.04) 3800,1092.04 ccw(c3885.96,1092.04) 3825.18,1031.25 3863.91,992.52 ccw(c3934.62,1063.23) 3934.62,963.23 4116.38,963.23 cw(c4116.38,937.2) 4142.41,937.2 ccw(c4163.15,937.2) 4163.15,916.47 4333.76,916.47 cw(c4333.76,877.41) 4372.81,877.41 ccw(c4387.29,877.41) 4387.29,862.93 4467.73,862.93 ccw(c4467.73,868.01) 4472.81,868.01 v1(4472.81,883.06)
4SRX_p: J1.Y31 U1.C1 | length 1014.4
  Top Layer w6.25: U1.C1@3650.36,1141.25 cw(c3665.17,1141.25) 3665.17,1156.06 3726.23,1156.06 cw(c3726.23,1092.04) 3790.25,1092.04 ccw(c3885.96,1092.04) 3818.28,1024.36 3857.02,985.63 ccw(c3934.62,1063.23) 3934.62,953.48 4116.38,953.48 cw(c4116.38,937.2) 4132.66,937.2 ccw(c4163.15,937.2) 4163.15,906.72 4333.76,906.72 cw(c4333.76,877.41) 4363.06,877.41 ccw(c4387.29,877.41) 4387.29,853.18 4467.73,853.18 cw(c4467.73,848.1) 4472.81,848.1 v1(4472.81,833.06)
5p5V_TRF_DCDC: C179.2 FB6.2 FC11.1 FC12.1 PP50.1 R179.1
  other v1: 776.82,2263.11 796.82,2263.11 816.82,2263.11 776.82,2283.11 796.82,2283.11 816.82,2283.11 2610.29,2295.1 2630.29,2295.1 2650.29,2295.1 2610.29,2315.1 2630.29,2315.1 2650.29,2315.1 328.4,2503.2 359,2502.99 1982.91,2576.67 2002.91,2576.67 1982.91,2596.67 2002.91,2596.67 1982.91,2616.67 2002.91,2616.67
5SRX_n: J1.A30 U1.D2 | length 1012.2
  Bottom Layer w6.25: v1(3610.99,1180.62) cw(c3605.56,1175.19) 3613.24,1175.19 3613.24,1172.21 ccw(c3619.64,1172.21) 3615.11,1167.69 ccw(c3619.64,1172.21) 3619.64,1165.81 3770.79,1165.81 cw(c3770.79,1140.7) 3795.9,1140.7 ccw(c3823.48,1140.7) 3823.48,1113.12 3824.73,1113.12 cw(c3824.73,1085.32) 3852.53,1085.32 3852.53,984.23 ccw(c3873.52,984.23) 3873.52,963.23 4076.2,963.23 cw(c4076.2,936.47) 4102.97,936.47 4102.97,931.55 ccw(c4121.89,931.55) 4121.89,912.63 4278.89,912.63 cw(c4278.89,888.86) 4302.66,888.86 4302.66,876.61 ccw(c4316.34,876.61) 4316.34,862.93 4363.97,862.93 ccw(c4363.97,871.77) 4372.81,871.77 J1.A30@4372.81,883.06
5SRX_p: J1.A31 U1.C2 | length 1012.6
  Bottom Layer w6.25: v1(3610.99,1141.25) ccw(c3605.56,1146.68) 3613.24,1146.68 3613.24,1149.66 cw(c3619.64,1149.66) 3615.11,1154.19 cw(c3619.64,1149.66) 3619.64,1156.06 3770.79,1156.06 cw(c3770.79,1140.7) 3786.15,1140.7 ccw(c3823.48,1140.7) 3823.48,1103.37 3824.73,1103.37 cw(c3824.73,1085.32) 3842.78,1085.32 3842.78,984.99 ccw(c3874.28,984.99) 3874.28,953.48 4080.24,953.48 cw(c4079.26,947.31) 4080.92,953.33 cw(c4076.2,936.47) 4093.07,941.19 cw(c4087.05,939.52) 4093.22,940.5 4093.22,931.55 ccw(c4121.89,931.55) 4121.89,902.88 4278.89,902.88 cw(c4278.89,888.86) 4292.91,888.86 4292.91,876.61 ccw(c4316.34,876.61) 4316.34,853.18 4363.97,853.18 cw(c4363.97,844.34) 4372.81,844.34 J1.A31@4372.81,833.06
5V_TRF: FB8.1 FB9.1 FC11.3 FC13.3 FC14.3 PP51.1
  other v1: 2931.3,270.97 2951.3,270.97 2931.3,290.97 2951.3,290.97 2800.69,728.39 2820.69,728.39 2800.69,748.39 2820.69,748.39 2950.39,760.03 2970.39,760.03 3030.26,761.71 3050.26,761.71 2950.39,780.03 2970.39,780.03 3030.26,781.71 3050.26,781.71 2799.7,2262.65 2819.7,2262.65 2799.7,2282.65 2819.7,2282.65 2799.7,2302.65 2819.7,2302.65 2723.47,2426.46 2743.47,2426.46 2763.47,2426.46 3459.56,2426.47 3479.56,2426.47 2723.47,2446.46 2743.47,2446.46 2763.47,2446.46 3459.56,2446.47 3479.56,2446.47
5V_TRF1: C189.1 C263.1 FB8.2 U41.9
5V_TRF2: C275.1 C276.1 FB9.2 U42.9
5V_TRF_EXT: FB10.1 J16.1
5V_Utility: C10.2 R6.2 R12.2 U5.1
  other v1: 292.6,1146.14 312.6,1146.14 332.6,1146.14
6SRX_n: J1.Z28 U1.G1 | length 992.5
  Top Layer w6.25: U1.G1@3650.36,1298.73 ccw(c3665.17,1298.73) 3665.17,1283.92 3807.25,1283.92 ccw(c3807.25,1316.01) 3829.94,1293.31 ; 3829.94,1293.32 3832.94,1296.32 cw(c3879.11,1250.15) 3879.11,1315.44 3903.4,1315.44 cw(c3903.4,1205.69) 3981,1283.3 4104.93,1159.37 cw(c4031.22,1085.66) 4135.46,1085.66 ccw(c4186.71,1085.66) 4150.47,1049.42 4181.12,1018.77 cw(c4151.98,989.63) 4193.19,989.63 ccw(c4219.89,989.63) 4219.89,962.93 4417.73,962.93 ccw(c4417.73,968.01) 4422.81,968.01 v1(4422.81,983.06)
6SRX_p: J1.Z29 U1.F1 | length 992.5
  Top Layer w6.25: U1.F1@3650.36,1259.36 cw(c3665.17,1259.36) 3665.17,1274.17 3807.25,1274.17 ccw(c3807.25,1316.01) 3836.84,1286.43 3839.83,1289.42 cw(c3879.11,1250.15) 3879.11,1305.69 3903.4,1305.69 cw(c3903.4,1205.69) 3974.11,1276.4 4098.04,1152.47 cw(c4031.22,1085.66) 4125.71,1085.66 ccw(c4186.71,1085.66) 4143.58,1042.53 4174.23,1011.88 cw(c4151.98,989.63) 4183.44,989.63 ccw(c4219.89,989.63) 4219.89,953.18 4373.43,953.18 4417.73,953.18 cw(c4417.73,948.1) 4422.81,948.1 v1(4422.81,933.06)
7SRX_n: J1.B28 U1.G2 | length 1006.9
  Bottom Layer w6.25: v1(3610.99,1298.73) cw(c3605.56,1293.31) 3613.24,1293.31 3613.24,1290.32 ccw(c3619.64,1290.32) 3615.11,1285.8 ccw(c3619.64,1290.33) 3619.64,1283.92 3759.94,1283.92 cw(c3759.94,1258.81) 3777.7,1276.57 ccw(c3810.36,1309.23) 3810.36,1263.04 3923.61,1263.04 cw(c3923.61,1233.82) 3952.84,1233.82 3952.84,1228.44 ; 3952.8,1228.44 3952.8,1033.06 ccw(c3973.23,1033.06) 3973.23,1012.63 4228.89,1012.63 cw(c4228.89,988.86) 4252.66,988.86 4252.66,976.61 ccw(c4266.34,976.61) 4266.34,962.93 4313.97,962.93 ccw(c4313.97,971.77) 4322.81,971.77 J1.B28@4322.81,983.06
7SRX_p: J1.B29 U1.F2 | length 1006.9
  Bottom Layer w6.25: v1(3610.99,1259.36) ccw(c3605.56,1264.79) 3613.24,1264.79 3613.24,1267.77 cw(c3619.64,1267.77) 3615.11,1272.3 cw(c3619.64,1267.77) 3619.64,1274.17 3759.94,1274.17 cw(c3759.94,1258.81) 3770.8,1269.67 ccw(c3810.36,1309.23) 3810.36,1253.29 3923.61,1253.29 cw(c3923.61,1233.82) 3943.09,1233.82 3943.09,1228.44 ; 3943.05,1228.44 3943.05,1033.06 ccw(c3973.23,1033.06) 3973.23,1002.88 4228.89,1002.88 cw(c4228.89,988.86) 4242.91,988.86 4242.91,976.61 ccw(c4266.34,976.61) 4266.34,953.18 4313.97,953.18 cw(c4313.97,944.34) 4322.81,944.34 J1.B29@4322.81,933.06
8SRX_n: J1.Y6 U1.T8 | length 1367
  Bottom Layer w6.25: v1(3374.77,1653.06) cw(c3380.19,1647.64) 3380.19,1655.31 3383.18,1655.31 ccw(c3383.18,1661.71) 3387.7,1657.19 ccw(c3383.17,1661.71) 3389.58,1661.71 3389.58,1772.67 cw(c3499.33,1772.67) 3421.72,1850.27 3602.23,2030.79 cw(c3679.84,1953.18) 3679.84,2062.93 4463.97,2062.93 ccw(c4463.97,2071.77) 4472.81,2071.77 J1.Y6@4472.81,2083.06
8SRX_p: J1.Y7 U1.T7 | length 1351.7
  Bottom Layer w6.25: v1(3414.14,1653.06) ccw(c3408.71,1647.64) 3408.71,1655.31 3405.73,1655.31 cw(c3405.73,1661.71) 3401.2,1657.19 cw(c3405.73,1661.71) 3399.33,1661.71 3399.33,1772.67 cw(c3499.33,1772.67) 3428.62,1843.38 3609.13,2023.89 cw(c3679.84,1953.18) 3679.84,2053.18 4463.97,2053.18 cw(c4463.97,2044.34) 4472.81,2044.34 J1.Y7@4472.81,2033.06
9SRX_n: J1.C2 U1.R8 | length 1382.7
  Bottom Layer w5: 3349.84,1670.39 3350.22,1670.02 3350.22,1650.32 ccw(c3372,1650.32) 3372,1628.54 3378.94,1628.54 cw(c3378.94,1616.08) 3387.74,1624.89 cw(c3382.4,1619.55) 3389.95,1619.55 cw(c3384.09,1619.55) 3384.09,1613.69 v1(3374.77,1613.69)
  Bottom Layer w6.25: 3349.84,1670.39 3349.84,1691.31 cw(c3370.81,1691.31) 3355.98,1706.13 ccw(c3354.75,1707.37) 3356.49,1707.37 3356.49,1824.01 cw(c3466.24,1824.01) 3388.64,1901.62 ; 3388.64,1901.62 3717.81,2230.79 cw(c3795.41,2153.18) 3795.41,2262.93 4263.97,2262.93 ccw(c4263.97,2271.77) 4272.81,2271.77 J1.C2@4272.81,2283.06
9SRX_p: J1.C3 U1.R7 | length 1366.1
  Bottom Layer w5: 3359.59,1670.43 3359.22,1670.06 3359.22,1653.16 ccw(c3374.85,1653.16) 3374.85,1637.54 3379.02,1637.54 cw(c3379.02,1616.29) 3394.04,1631.31 3394.15,1631.21 cw(c3382.54,1619.61) 3398.95,1619.61 3398.95,1619.55 ccw(c3404.81,1619.55) 3404.81,1613.69 v1(3414.14,1613.69)
  Bottom Layer w6.25: 3359.59,1670.43 3359.59,1691.31 cw(c3370.81,1691.31) 3362.88,1699.24 ccw(c3354.75,1707.37) 3366.24,1707.37 3366.24,1824.01 cw(c3466.24,1824.01) 3395.53,1894.72 3724.7,2223.89 cw(c3795.41,2153.18) 3795.41,2253.18 4263.97,2253.18 cw(c4263.97,2244.34) 4272.81,2244.34 J1.C3@4272.81,2233.06
10SRX_n: J1.Z8 U1.T5 | length 1168.4
  Bottom Layer w6.25: v1(3492.88,1653.06) cw(c3498.31,1647.64) 3498.31,1655.31 3501.29,1655.31 ccw(c3501.29,1661.71) 3505.81,1657.19 ccw(c3501.29,1661.71) 3507.69,1661.71 3507.69,1790.89 cw(c3617.44,1790.89) 3539.83,1868.49 3604.09,1932.75 cw(c3676.95,1859.9) 3676.95,1962.93 4413.97,1962.93 ccw(c4413.97,1971.77) 4422.81,1971.77 J1.Z8@4422.81,1983.06
10SRX_p: J1.Z9 U1.T4 | length 1153.1
  Bottom Layer w6.25: v1(3532.25,1653.06) ccw(c3526.82,1647.64) 3526.82,1655.31 3523.84,1655.31 cw(c3523.84,1661.71) 3519.31,1657.19 cw(c3523.84,1661.71) 3517.44,1661.71 3517.44,1790.89 cw(c3617.44,1790.89) 3546.73,1861.6 3610.99,1925.86 cw(c3676.95,1859.9) 3676.95,1953.18 4413.97,1953.18 cw(c4413.97,1944.34) 4422.81,1944.34 J1.Z9@4422.81,1933.06
11SRX_n: J1.A22 U1.R5 | length 1417.1
  Bottom Layer w5: v1(3492.88,1613.69) 3502.2,1613.69 ccw(c3502.2,1619.55) 3508.06,1619.55 3508.06,1619.61 cw(c3524.47,1619.61) 3512.87,1631.21 3512.97,1631.31 cw(c3527.99,1616.29) 3527.99,1637.54 3532.17,1637.54 ccw(c3532.17,1653.16) 3547.8,1653.16 3547.8,1670.06
  Bottom Layer w6.25: 3547.05,1669.98 3547.05,1700.89 cw(c3573.27,1700.89) 3573.27,1727.12 3693.64,1727.12 cw(c3693.64,1701.74) 3711.59,1719.68 ccw(c3726.7,1734.79) 3726.7,1713.42 4272.21,1713.42 cw(c4272.21,1683.06) 4302.58,1683.06 4302.58,1276.69 ccw(c4316.34,1276.69) 4316.34,1262.93 4363.97,1262.93 ccw(c4363.97,1271.77) 4372.81,1271.77 J1.A22@4372.81,1283.06
11SRX_p: J1.A23 U1.R4 | length 1402.9
  Bottom Layer w5: v1(3532.25,1613.69) 3522.92,1613.69 cw(c3522.92,1619.55) 3517.06,1619.55 cw(c3524.61,1619.55) 3519.27,1624.89 cw(c3528.08,1616.08) 3528.08,1628.54 3535.01,1628.54 ccw(c3535.01,1650.32) 3556.8,1650.32 3556.8,1670.02
  Bottom Layer w6.25: 3556.8,1670.02 3556.8,1700.89 cw(c3573.27,1700.89) 3573.27,1717.37 3693.64,1717.37 cw(c3693.64,1701.74) 3704.69,1712.79 ccw(c3726.7,1734.79) 3726.7,1703.67 4272.21,1703.67 cw(c4272.21,1683.06) 4292.83,1683.06 4292.83,1276.69 ccw(c4316.34,1276.69) 4316.34,1253.18 4363.97,1253.18 cw(c4363.97,1244.34) 4372.81,1244.34 J1.A23@4372.81,1233.06
12SRX_n: J1.Z24 U1.P1 | length 1135.6
  Top Layer w6.25: U1.P1@3650.36,1574.32 ccw(c3665.17,1574.32) 3665.17,1559.51 4143.05,1559.51 cw(c4143.05,1449.76) 4252.8,1449.76 4252.8,1192.51 ccw(c4282.39,1192.51) 4282.39,1162.93 4417.73,1162.93 ccw(c4417.73,1168.01) 4422.81,1168.01 v1(4422.81,1183.06)
12SRX_p: J1.Z25 U1.N1 | length 1134.9
  Top Layer w6.25: U1.N1@3650.36,1534.95 cw(c3665.17,1534.95) 3665.17,1549.76 4143.05,1549.76 cw(c4143.05,1449.76) 4243.05,1449.76 4243.05,1216.05 ccw(c4305.92,1216.05) 4243.51,1208.47 cw(c4237.3,1207.75) 4243.55,1207.79 4243.55,1192.51 ccw(c4282.39,1192.51) 4282.39,1153.68 4297.66,1153.68 cw(c4297.62,1147.43) 4298.34,1153.64 ccw(c4305.92,1216.05) 4305.92,1153.18 4417.73,1153.18 cw(c4417.73,1148.1) 4422.81,1148.1 v1(4422.81,1133.06)
12V: C7.2 C9.2 C15.2 C16.2 C28.2 C29.2 C30.2 C31.2 C39.2 C40.2 C174.2 C175.2 D3.1 R1.1 R7.2 R9.2 R11.2 R25.2 R35.2 R49.2 R178.2 U3.D1 U3.D2 U4.6 U5.6 U7.18 U9.8 U9.12 U11.18 U39.18 | length 127.3
  Bottom Layer w8: U3.D2@1075.34,362.22 1075.34,347.6 1089.04,333.89 1089.04,326.18 1103,312.22 1110.71,312.22 1110.71,342.6 U3.D1@1091.09,362.22
  other v1: 397.23,91.58 1095.71,242.22 1115.71,242.22 1135.71,242.22 1155.71,242.22 1095.71,262.22 1115.71,262.22 1135.71,262.22 1155.71,262.22 1095.71,282.22 1115.71,282.22 1135.71,282.22 1155.71,282.22 95.4,779.98 248.69,988.68 248.84,1019.68 248.84,1039.68 248.84,1059.68 60.83,1123.27 80.83,1123.27 100.83,1123.27 61.46,1205.2 60.83,1323.27 80.83,1323.27 100.83,1323.27 475.4,1365.51 495.4,1365.51 515.4,1365.51 61.46,1405.2 1017.38,1806.54 911.59,1817.43 1017.38,1826.54 1017.38,1846.54 1002.37,1877.84 1002.37,2058.54 1002.53,2105.59 1002.53,2125.59 1002.53,2145.59 879.64,2254.63 512.44,2325.3 512.44,2345.3 512.44,2365.3 512.28,2396.3 1032.92,2463.32 1033.08,2494.32 1033.08,2514.32 1033.08,2534.32 359,2604.99
12V_FMC: J1.C35 J1.C37 J1.L36 J1.L37 J1.L40 PP46.1 SW1.3
  other v1: 3872.81,383.06 3872.81,533.06 4272.81,533.06 3872.81,583.06 4272.81,633.06
13SRX_n: J1.B24 U1.P2 | length 1117.3
  Bottom Layer w6.25: v1(3610.99,1574.32) cw(c3605.56,1568.9) 3613.24,1568.9 3613.24,1565.92 ccw(c3619.64,1565.92) 3615.11,1561.39 ccw(c3619.64,1565.92) 3619.64,1559.51 3730.59,1559.51 3733.5,1562.42 4153.32,1562.42 cw(c4153.32,1552.68) 4155.77,1562.11 ccw(c4157.29,1568.17) 4157.25,1561.92 4168.9,1561.92 ccw(c4168.87,1568.17) 4170.37,1562.1 cw(c4172.79,1552.68) 4172.79,1562.41 cw(c4172.81,1532.78) 4202.44,1532.78 4202.44,1184.67 ccw(c4224.18,1184.67) 4224.18,1162.93 4313.97,1162.93 ccw(c4313.97,1171.77) 4322.81,1171.77 J1.B24@4322.81,1183.06
13SRX_p: J1.B25 U1.N2 | length 1117
  Bottom Layer w6.25: v1(3610.99,1534.95) ccw(c3605.56,1540.38) 3613.24,1540.38 3613.24,1543.36 cw(c3619.64,1543.36) 3615.11,1547.89 cw(c3619.64,1543.36) 3619.64,1549.76 3734.63,1549.76 3737.54,1552.67 3822.04,1552.67 ccw(c3822.01,1558.92) 3822.19,1552.67 cw(c3822.81,1533.06) 3823.41,1552.67 ccw(c3823.61,1558.92) 3823.57,1552.67 3872.04,1552.67 ccw(c3872.01,1558.92) 3872.19,1552.67 cw(c3872.81,1533.06) 3873.41,1552.67 ccw(c3873.61,1558.92) 3873.57,1552.67 3922.04,1552.67 ccw(c3922.01,1558.92) 3922.19,1552.67 cw(c3922.81,1533.06) 3923.41,1552.67 ccw(c3923.61,1558.92) 3923.57,1552.67 3972.04,1552.67 ccw(c3972.01,1558.92) 3972.19,1552.67 cw(c3972.81,1533.06) 3973.41,1552.67 ccw(c3973.61,1558.92) 3973.57,1552.67 4022.04,1552.67 ccw(c4022.01,1558.92) 4022.19,1552.67 cw(c4022.81,1533.06) 4023.41,1552.67 ccw(c4023.61,1558.92) 4023.57,1552.67 4072.04,1552.67 ccw(c4072.01,1558.92) 4072.19,1552.67 cw(c4072.81,1533.06) 4073.41,1552.67 ccw(c4073.61,1558.92) 4073.57,1552.67 4122.04,1552.67 ccw(c4122.01,1558.92) 4122.19,1552.67 cw(c4122.81,1533.06) 4123.41,1552.67 ccw(c4123.61,1558.92) 4123.57,1552.67 4172.04,1552.67 ccw(c4172.01,1558.92) 4172.19,1552.67 cw(c4172.81,1533.06) 4172.81,1552.68 cw(c4172.81,1533.06) 4173.71,1552.66 ccw(c4173.96,1558.9) 4173.89,1552.66 cw(c4173.8,1533.77) 4192.69,1533.77 4192.69,1187.06 ccw(c4226.56,1187.06) 4193.86,1178.23 cw(c4187.81,1176.63) 4193.91,1178.01 ccw(c4224.18,1184.67) 4217.47,1154.41 cw(c4216.14,1148.31) 4217.74,1154.35 ccw(c4226.56,1187.06) 4226.56,1153.18 4313.97,1153.18 cw(c4313.97,1144.34) 4322.81,1144.34 J1.B25@4322.81,1133.06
